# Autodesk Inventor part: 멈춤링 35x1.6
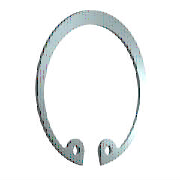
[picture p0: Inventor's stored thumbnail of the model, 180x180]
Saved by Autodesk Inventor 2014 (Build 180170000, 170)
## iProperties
IsCustomPart: 1
Created: 2012-02
Part Number: 멈춤링 35x1.6
Material: 강철, 연강
Description: 리테이닝 링(C형)
Document SubType Name: Modeling
Standard: KS B 1336
Designer: mduedu
Standards Organization: KS
Language: ko-KR
Size Designation: 35x1.6
Categories: <MemberInstance><Categories><Category DisplayName="샤프트 부품" InternalName="7f7aeb1f-a693-4053-b835-cee3144e0d98" Mnemonic="SHFT"><Category DisplayName="써클립" Inter
Density: 1 g/cm^3
Appearance: 파란색 - 벽 페인트 - 광택
Author: mduedu
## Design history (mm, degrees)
sketch "스케치1"
  geometry: L1 (0, 15.113)-(0, -73.177) reference; L2 (-45.5, 0)-(45.5, 0) reference; L3 (-4.964, 1)-(1.502, 1); L4 (0, -2.5)-(-5.307, -2.5); L5 (0, -17.5)-(-8.583, -33.888); L6 (-8.583, -33.888)-(-21.772, -26.981); L7 (-7.377, -31.585)-(-17.631, -26.214); L8 (-5.162, -32.745)-(-6.29, -34.898); L9 (5.162, -32.745)-(6.29, -34.898); C1 r 1.25 at (-7.377, -31.585); C2 r 1.25 at (7.377, -31.585); A1 r 15.875 centre (0, -18.375) between (11.82, -28.972) and (-11.82, -28.972); A2 r 18.5 centre (0, -17.5) between (6.29, -34.898) and (-6.29, -34.898); A3 r 2.5 centre (-7.377, -31.585) between (-5.162, -32.745) and (-8.668, -29.444); A4 r 2.5 centre (-9.959, -27.303) between (-11.82, -28.972) and (-8.668, -29.444); A5 r 2.5 centre (9.959, -27.303) between (8.668, -29.444) and (11.82, -28.972); A6 r 2.5 centre (7.377, -31.585) between (8.668, -29.444) and (5.162, -32.745); 3 further points
  constraints: 15 point on circle, 14 end point, 9 symmetric about line, 8 centre point, 6 tangent, 4 coincident, 4 point on line, 3 perpendicular, 1 parallel, 4 other
  dimensions: "d8" = 0.875 distance of A1.centre L5.start (= 0.25 x SRB1); "d38" = 3.5 distance between parallel lines of L4 L3 (= SRB1); "d39" = 17.5 distance from line of L5.start L2 (= 0.5 x WD); "d43" = 18.5 radius of A2 (= 0.5 x ND); "d45" = 2.6 distance between parallel lines of L7 L6 (= 0.5 x SRB2); "d46" = 2.5 radius of A4 (= SD5); "d47" = 6.29 distance from line of L1 L8.end (= 0.17 x ND); "d48" = 2.5 diameter of C1 (= SD5); "d49" = 2.5 radius of A3 (= SD5)
extrude "본체" new body sketch "스케치1" distance "d2" = 1.6 (= SD); taper "d3" = 0 deg
workaxis "Work Axis1"
workaxis "Work Axis2"
workplane "Work Plane1"
body "Solid1"
other parameters: "WD" = 35 [user parameter; used in 3 equation terms], "SD" = 1.6 [user parameter; used in 1 equation term], "SRB1" = 3.5 [user parameter; used in 2 equation terms], "ND" = 37 [user parameter; used in 2 equation terms], "SRB2" = 5.2 [user parameter; used in 1 equation term], "SD5" = 2.5 [user parameter; used in 3 equation terms], "d50" = 0, "d51" = 0, "d52" = 0, "d53" = 0, "WDMIN" = 34 [user parameter], "SD6" = 37.8 [user parameter], "WDMAX" = 35 (= WD) [user parameter], "NND" = 35 (= WD) [user parameter]
